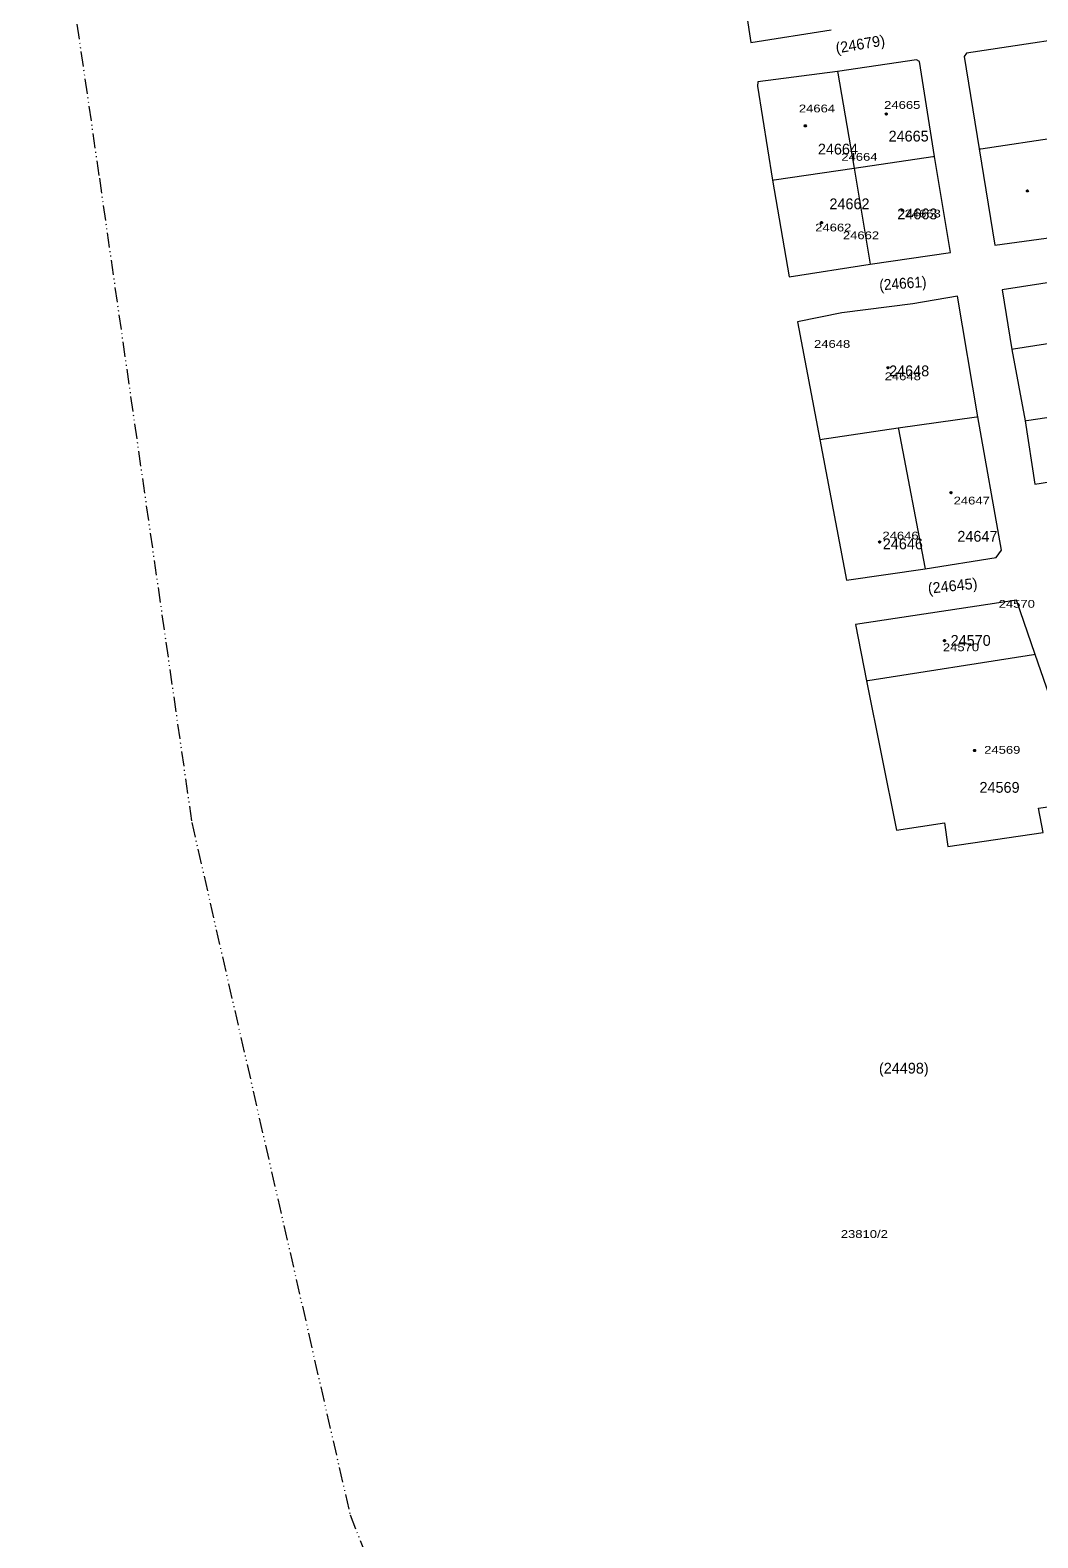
# Model space of a CAD drawing. Extents: x 649608 to 651081, y 237980 to 241202.
# Drawn here: x 649608 to 649945, y 239441 to 239944 of the extents above; entities that cross this region are included whole.
import ezdxf

# ---------------------------------------------------------------- set-up
doc = ezdxf.new("R2010")
doc.units = 0
doc.header["$PDMODE"] = 32
doc.header["$PDSIZE"] = 0.5
doc.linetypes.add('DASH_DOUBLE_DOT', pattern=[9.2, 5, -1.2, 0.3, -1.2, 0.3, -1.2])
for name, color, linetype in [('19', 7, 'Continuous'), ('20', 7, 'Continuous'), ('6', 7, 'Continuous')]:
    doc.layers.add(name, color=color, linetype=linetype)
for name, color, linetype, lineweight in [('3', 7, 'Continuous', 13), ('5', 7, 'Continuous', 13), ('52', 7, 'DASH_DOUBLE_DOT', 13)]:
    doc.layers.add(name, color=color, linetype=linetype, lineweight=lineweight)

msp = doc.modelspace()

# ---------------------------------------------------------------- linework, layer by layer
at = {"layer": '3'}
for p, q in [((649915.682, 239869.667), (649910.302, 239901.779)), ((649880.904, 239760.389), (649907.226, 239764.219)), ((649883.998, 239745.591), (649887.601, 239726.78))]:
    msp.add_line(p, q, dxfattribs=at)
for points in [[(649843.637, 239974.808), (649849.023, 239939.796), (649875.782, 239944.051)], [(649971.163, 239943.727), (649921.048, 239936.253), (649920.249, 239935.149), (649925.279, 239904.249)], [(649910.302, 239901.779), (649905.276, 239933.385), (649904.336, 239933.997), (649877.988, 239930.066)], [(649877.988, 239930.066), (649851.311, 239926.592), (649851.276, 239925.256), (649856.303, 239893.877)], [(649925.279, 239904.249), (649930.506, 239872.163), (649957.389, 239875.837), (649980.824, 239879.434), (650003.468, 239882.936), (650025.624, 239886.164), (650047.782, 239889.543)], [(649856.303, 239893.877), (649861.759, 239861.588), (649888.849, 239865.841), (649915.682, 239869.667)], [(650017.104, 239825.198), (650010.78, 239868.992), (649973.06, 239863.45), (649932.936, 239857.269)], [(649932.936, 239857.269), (649936.2, 239837.325), (649940.588, 239813.566)], [(649924.844, 239814.91), (649918.063, 239855.176), (649903.136, 239852.631), (649879.449, 239849.54), (649864.622, 239846.615), (649872.048, 239807.327), (649880.904, 239760.389)], [(649940.588, 239813.566), (649943.87, 239792.463), (649954.323, 239794.056), (649957.658, 239773.33), (649973.172, 239775.796), (649969.835, 239796.295), (650020.206, 239803.868), (650017.104, 239825.198)], [(649907.226, 239764.219), (649930.943, 239767.965), (649932.695, 239770.349), (649924.844, 239814.91)], [(649887.601, 239726.78), (649897.69, 239677.034), (649913.663, 239679.422), (649914.76, 239671.546), (649946.602, 239676.221), (649945.098, 239684.275), (649961.019, 239686.562), (649943.929, 239735.574), (649937.717, 239753.671), (649883.998, 239745.591)]]:
    msp.add_lwpolyline(points, dxfattribs=at)
at = {"layer": '5'}
msp.add_line((649872.048, 239807.327), (649898.242, 239811.233), dxfattribs=at)
for points in [[(649877.988, 239930.066), (649878.073, 239929.566), (649883.469, 239897.802), (649888.849, 239865.841)], [(649925.279, 239904.249), (649925.779, 239904.325), (649952.395, 239908.351), (649975.754, 239912.049), (649975.541, 239914.522), (649997.799, 239917.622), (649998.37, 239915.198), (650020.705, 239918.5), (650042.709, 239921.779)], [(649883.469, 239897.802), (649909.802, 239901.705), (649910.302, 239901.779)], [(649856.303, 239893.877), (649856.803, 239893.949), (649883.469, 239897.802)], [(649975.763, 239843.561), (649975.263, 239843.482), (649936.7, 239837.404), (649936.2, 239837.325)], [(649940.588, 239813.566), (649941.088, 239813.64), (649979.535, 239819.302)], [(649898.242, 239811.233), (649924.344, 239814.841), (649924.844, 239814.91)], [(649898.242, 239811.233), (649898.338, 239810.733), (649907.13, 239764.719), (649907.226, 239764.219)], [(649943.929, 239735.574), (649943.429, 239735.496), (649888.101, 239726.858), (649887.601, 239726.78)]]:
    msp.add_lwpolyline(points, dxfattribs=at)
at = {"layer": '52'}
msp.add_lwpolyline([(649701.481, 241202.319), (649640.936, 240904.262), (649608.393, 240352.424), (649614.771, 240009.578), (649631.5, 239894.49), (649662.347, 239679.564), (649715.192, 239448.546), (649776.71, 239295.263), (649918.979, 238940.568), (649995.713, 238777.318), (650020.382, 238724.355), (650126.69, 238550.145), (650295.37, 238327.169), (650466.153, 238100.489), (650557.889, 237992.529), (650568.158, 237979.989)], dxfattribs=at)
at = {"layer": '6'}
for p in [(649867.233, 239911.971), (649894.226, 239915.899), (649941.366, 239890.257), (649899.568, 239883.81), (649872.608, 239879.695), (649894.809, 239831.251), (649915.846, 239789.564), (649892.017, 239773.1), (649913.679, 239740.225), (649923.701, 239703.56)]:
    msp.add_point(p, dxfattribs=at)

# ---------------------------------------------------------------- texts
at = {"layer": '19'}
for s, rotation, p in [('(24679)', 9.472, (649877.652, 239936.092)), ('(24645)', 6.141, (649908.32, 239755.842))]:
    msp.add_text(s, height=3.6, rotation=rotation, dxfattribs=at).set_placement(p)
for s, p in [('24665', (649895.005, 239906.735)), ('24664', (649871.4, 239902.408)), ('24662', (649875.255, 239884.142)), ('24663', (649897.895, 239880.778)), ('24648', (649895.179, 239828.412)), ('24647', (649917.976, 239773.228)), ('24646', (649893.069, 239770.7)), ('24570', (649915.717, 239738.494)), ('24569', (649925.352, 239689.464)), ('(24498)', (649891.793, 239595.777))]:
    msp.add_text(s, height=3.6, dxfattribs=at).set_placement(p)
at = {"layer": '19', "width": 0.95}
msp.add_text('(24661)', height=3.6, rotation=4.246, dxfattribs=at).set_placement((649892.04, 239857.063))
at = {"layer": '20', "width": 1.25}
for s, p in [('24664', (649865.057, 239916.456)), ('24665', (649893.526, 239917.631)), ('24664', (649879.229, 239900.311)), ('24663', (649900.356, 239881.39)), ('24662', (649870.504, 239876.736)), ('24662', (649879.755, 239874.141)), ('24648', (649870.119, 239837.898)), ('24648', (649893.692, 239827.105)), ('24647', (649916.721, 239785.643)), ('24646', (649892.953, 239773.961)), ('24570', (649931.777, 239751.19)), ('24570', (649913.141, 239736.689)), ('24569', (649926.925, 239702.476)), ('23810/2', (649879.061, 239540.944))]:
    msp.add_text(s, height=2.6, dxfattribs=at).set_placement(p)

doc.saveas('drawing.dxf')
